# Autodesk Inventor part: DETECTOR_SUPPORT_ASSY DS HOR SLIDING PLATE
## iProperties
Shininess: 64.0
Length Units: 11272
Angle Units: 11279
Time Units: 11290
Mass Units: 11286
Length Display Precision: 3
Angle Display Precision: 2
Compacted: True
Part Number: DETECTOR_SUPPORT_ASSY DS HOR SLIDING PLATE
Document SubType Name: Modeling
Created: 2004-08
Designer: John Blackburn
Material: MILD_STEEL
Manufacturer: Standard
Standards Organization: Custom
Density: 0.0
Volumn: 0.0
Area: 0.0
PropertySet Name: Model Information
Control State: 0
Master: False
Checked Out: False
Author: John Blackburn
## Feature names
1. ExtrusionMidplane1
2. ExtrusionThru1
